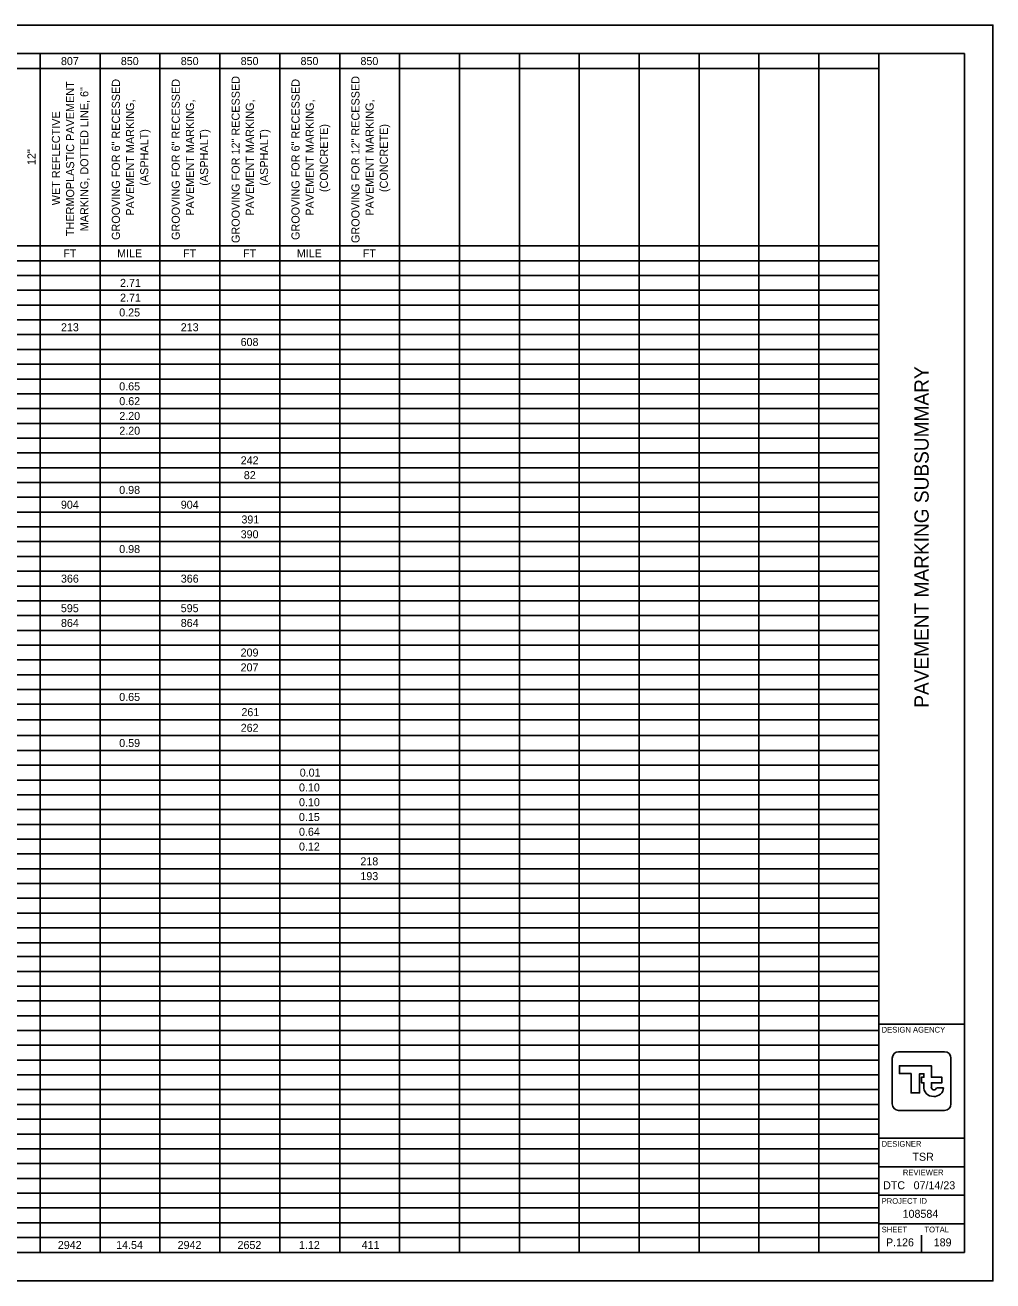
# Model space of a CAD drawing. Extents: x 0 to 34, y 0 to 22.
# Drawn here: x 17.04 to 34, y 0 to 22 of the extents above; entities that cross this region are included whole.
import ezdxf

# ---------------------------------------------------------------- set-up
doc = ezdxf.new("R2010")
doc.units = 0
for name, color, linetype in [('SH_Border', 7, 'Continuous'), ('SH_Cut_Line', 7, 'Continuous'), ('SH_Data', 7, 'Continuous'), ('SH_Text', 7, 'Continuous')]:
    doc.layers.add(name, color=color, linetype=linetype)

msp = doc.modelspace()

# ---------------------------------------------------------------- linework, layer by layer
at = {"layer": 'SH_Border'}
for p, q in [((32, 0.5), (32, 21.5)), ((32, 4.5), (33.5, 4.5)), ((32, 2.5), (33.5, 2.5)), ((32, 2), (33.5, 2)), ((32, 1.5), (33.5, 1.5)), ((32, 1), (33.5, 1))]:
    msp.add_line(p, q, dxfattribs=at)
msp.add_lwpolyline([(1.5, 21.5), (33.5, 21.5), (33.5, 0.5), (1.5, 0.5)], close=True, dxfattribs=at)
at = {"layer": 'SH_Cut_Line'}
msp.add_lwpolyline([(0, 0), (34, 0), (34, 22), (0, 22)], close=True, dxfattribs=at)
at = {"layer": 'SH_Data'}
for p, q in [((32.75, 3.5), (32.75, 3.5)), ((32.791, 3.415), (32.791, 3.415)), ((33.136, 3.385), (33.015, 3.385)), ((32.375, 0.675), (32.375, 0.675)), ((32.75, 0.5), (32.75, 0.8))]:
    msp.add_line(p, q, dxfattribs=at)
for points in [[(32.348, 4.014), (33.152, 4.014)], [(32.236, 3.099), (32.236, 3.901)], [(32.922, 3.399), (32.922, 3.47), (33.107, 3.47), (33.107, 3.568), (32.922, 3.568), (32.922, 3.768), (32.361, 3.768), (32.361, 3.632), (32.566, 3.632), (32.566, 3.294), (32.715, 3.294), (32.715, 3.63), (32.79, 3.63), (32.79, 3.568), (32.748, 3.568), (32.748, 3.47), (32.79, 3.47), (32.79, 3.415), (32.791, 3.415)], [(33.264, 3.901), (33.264, 3.099)], [(33.152, 2.986), (32.348, 2.986)]]:
    msp.add_lwpolyline(points, dxfattribs=at)
for centre, radius, start, end in [((32.348, 3.901), 0.113, 90, 180), ((33.152, 3.901), 0.113, 360, 90), ((32.949, 3.392), 0.16, 171.8856, 274.8323), ((32.968, 3.392), 0.0473, 171.8856, 350.9243), ((32.976, 3.392), 0.16, 265.1677, 357.3201), ((32.348, 3.099), 0.113, 180, 270), ((33.152, 3.099), 0.113, 270, 360)]:
    msp.add_arc(centre, radius, start, end, dxfattribs=at)
at = {"layer": 'SH_Text'}
for p, q in [((1.5, 21.5), (32, 21.5)), ((17.306, 21.5), (17.306, 0.5)), ((18.355, 21.5), (18.355, 0.5)), ((19.405, 21.5), (19.405, 0.5)), ((20.454, 21.5), (20.454, 0.5)), ((21.504, 21.5), (21.504, 0.5)), ((22.554, 21.5), (22.554, 0.5)), ((23.603, 21.5), (23.603, 0.5)), ((24.653, 21.5), (24.653, 0.5)), ((25.702, 21.5), (25.702, 0.5)), ((26.752, 21.5), (26.752, 0.5)), ((27.802, 21.5), (27.802, 0.5)), ((28.851, 21.5), (28.851, 0.5)), ((29.901, 21.5), (29.901, 0.5)), ((30.95, 21.5), (30.95, 0.5)), ((32, 21.5), (32, 0.5)), ((8.909, 21.241), (32, 21.241)), ((8.909, 18.132), (32, 18.132)), ((8.909, 17.873), (32, 17.873)), ((1.5, 17.614), (32, 17.614)), ((1.5, 17.355), (32, 17.355)), ((1.5, 17.096), (32, 17.096)), ((1.5, 16.837), (32, 16.837)), ((1.5, 16.578), (32, 16.578)), ((1.5, 16.319), (32, 16.319)), ((1.5, 16.06), (32, 16.06)), ((1.5, 15.8), (32, 15.8)), ((1.5, 15.541), (32, 15.541)), ((1.5, 15.282), (32, 15.282)), ((1.5, 15.023), (32, 15.023)), ((1.5, 14.764), (32, 14.764)), ((1.5, 14.505), (32, 14.505)), ((1.5, 14.246), (32, 14.246)), ((1.5, 13.987), (32, 13.987)), ((1.5, 13.728), (32, 13.728)), ((1.5, 13.469), (32, 13.469)), ((1.5, 13.21), (32, 13.21)), ((1.5, 12.951), (32, 12.951)), ((1.5, 12.692), (32, 12.692)), ((1.5, 12.433), (32, 12.433)), ((1.5, 12.173), (32, 12.173)), ((1.5, 11.914), (32, 11.914)), ((1.5, 11.655), (32, 11.655)), ((1.5, 11.396), (32, 11.396)), ((1.5, 11.137), (32, 11.137)), ((1.5, 10.878), (32, 10.878)), ((1.5, 10.619), (32, 10.619)), ((1.5, 10.36), (32, 10.36)), ((1.5, 10.101), (32, 10.101)), ((1.5, 9.827), (32, 9.827)), ((1.5, 9.552), (32, 9.552)), ((1.5, 9.293), (32, 9.293)), ((1.5, 9.034), (32, 9.034)), ((1.5, 8.775), (32, 8.775)), ((1.5, 8.516), (32, 8.516)), ((1.5, 8.257), (32, 8.257)), ((1.5, 7.998), (32, 7.998)), ((1.5, 7.739), (32, 7.739)), ((1.5, 7.48), (32, 7.48)), ((1.5, 7.221), (32, 7.221)), ((1.5, 6.962), (32, 6.962)), ((1.5, 6.702), (32, 6.702)), ((1.5, 6.443), (32, 6.443)), ((1.5, 6.184), (32, 6.184)), ((1.5, 5.925), (32, 5.925)), ((1.5, 5.681), (32, 5.681)), ((1.5, 5.422), (32, 5.422)), ((1.5, 5.163), (32, 5.163)), ((1.5, 4.904), (32, 4.904)), ((1.5, 4.645), (32, 4.645)), ((1.5, 4.386), (32, 4.386)), ((1.5, 4.127), (32, 4.127)), ((1.5, 3.868), (32, 3.868)), ((1.5, 3.609), (32, 3.609)), ((1.5, 3.35), (32, 3.35)), ((1.5, 3.091), (32, 3.091)), ((1.5, 2.832), (32, 2.832)), ((1.5, 2.573), (32, 2.573)), ((1.5, 2.313), (32, 2.313)), ((1.5, 2.054), (32, 2.054)), ((1.5, 1.795), (32, 1.795)), ((1.5, 1.536), (32, 1.536)), ((1.5, 1.277), (32, 1.277)), ((1.5, 1.018), (32, 1.018)), ((1.5, 0.759), (32, 0.759)), ((1.5, 0.5), (32, 0.5))]:
    msp.add_line(p, q, dxfattribs=at)

# ---------------------------------------------------------------- texts
at = {"layer": 'SH_Data'}
msp.add_text('PAVEMENT MARKING SUBSUMMARY', height=0.25, rotation=90, dxfattribs=at).set_placement((32.875, 10.041))
for s, height, p in [('DESIGN AGENCY', 0.1, (32.05, 4.35)), ('DESIGNER', 0.1, (32.05, 2.35)), ('TSR', 0.14, (32.59, 2.105)), ('REVIEWER', 0.1, (32.422, 1.85)), ('DTC', 0.14, (32.076, 1.605)), ('07/14/23', 0.14, (32.611, 1.605)), ('PROJECT ID', 0.1, (32.05, 1.35)), ('108584', 0.14, (32.418, 1.105)), ('SHEET', 0.1, (32.05, 0.85)), ('TOTAL', 0.1, (32.8, 0.85)), ('P.126', 0.14, (32.127, 0.605)), ('189', 0.14, (32.963, 0.605))]:
    msp.add_text(s, height=height, dxfattribs=at).set_placement(p)
at = {"layer": 'SH_Text'}
for s, p in [('807', (17.67, 21.3)), ('850', (18.719, 21.3)), ('850', (19.769, 21.3)), ('850', (20.819, 21.3)), ('850', (21.868, 21.3)), ('850', (22.918, 21.3)), ('FT', (17.711, 17.932)), ('MILE', (18.654, 17.932)), ('FT', (19.81, 17.932)), ('FT', (20.86, 17.932)), ('MILE', (21.803, 17.932)), ('FT', (22.959, 17.932)), ('2.71', (18.705, 17.414)), ('2.71', (18.705, 17.155)), ('0.25', (18.691, 16.896)), ('213', (17.67, 16.637)), ('213', (19.769, 16.637)), ('608', (20.818, 16.378)), ('0.65', (18.691, 15.601)), ('0.62', (18.692, 15.342)), ('2.20', (18.692, 15.083)), ('2.20', (18.692, 14.824)), ('242', (20.819, 14.305)), ('82', (20.874, 14.046)), ('0.98', (18.691, 13.787)), ('904', (17.67, 13.528)), ('904', (19.769, 13.528)), ('391', (20.832, 13.269)), ('390', (20.819, 13.01)), ('0.98', (18.691, 12.751)), ('366', (17.67, 12.233)), ('366', (19.769, 12.233)), ('595', (17.669, 11.715)), ('595', (19.768, 11.715)), ('864', (17.67, 11.456)), ('864', (19.769, 11.456)), ('209', (20.818, 10.938)), ('207', (20.818, 10.678)), ('0.65', (18.691, 10.16)), ('261', (20.832, 9.894)), ('262', (20.819, 9.619)), ('0.59', (18.691, 9.353)), ('0.01', (21.854, 8.834)), ('0.10', (21.841, 8.575)), ('0.10', (21.841, 8.316)), ('0.15', (21.84, 8.057)), ('0.64', (21.841, 7.798)), ('0.12', (21.841, 7.539)), ('218', (22.917, 7.28)), ('193', (22.917, 7.021)), ('2942', (17.615, 0.559)), ('14.54', (18.637, 0.559)), ('2942', (19.714, 0.559)), ('2652', (20.764, 0.559)), ('1.12', (21.841, 0.559)), ('411', (22.939, 0.559))]:
    msp.add_text(s, height=0.1402, dxfattribs=at).set_placement(p)
for s, p in [('THERMOPLASTIC PAVEMENT ', (17.901, 18.304)), ('MARKING, DOTTED LINE, 6"', (18.15, 18.388)), ('GROOVING FOR 6" RECESSED ', (18.703, 18.236)), ('GROOVING FOR 6" RECESSED ', (19.752, 18.236)), ('GROOVING FOR 12" RECESSED ', (20.802, 18.182)), ('GROOVING FOR 6" RECESSED ', (21.851, 18.236)), ('GROOVING FOR 12" RECESSED ', (22.901, 18.182)), ('PAVEMENT MARKING, ', (18.951, 18.661)), ('PAVEMENT MARKING, ', (20.001, 18.661)), ('PAVEMENT MARKING, ', (21.05, 18.661)), ('PAVEMENT MARKING, ', (22.1, 18.661)), ('PAVEMENT MARKING, ', (23.149, 18.661)), ('WET REFLECTIVE ', (17.653, 18.844)), ('(CONCRETE)', (22.348, 19.075)), ('(CONCRETE)', (23.398, 19.075)), ('(ASPHALT)', (19.2, 19.186)), ('(ASPHALT)', (20.249, 19.186)), ('(ASPHALT)', (21.299, 19.186)), ('12"', (17.225, 19.547))]:
    msp.add_text(s, height=0.142, rotation=90, dxfattribs=at).set_placement(p)

doc.saveas('drawing.dxf')
